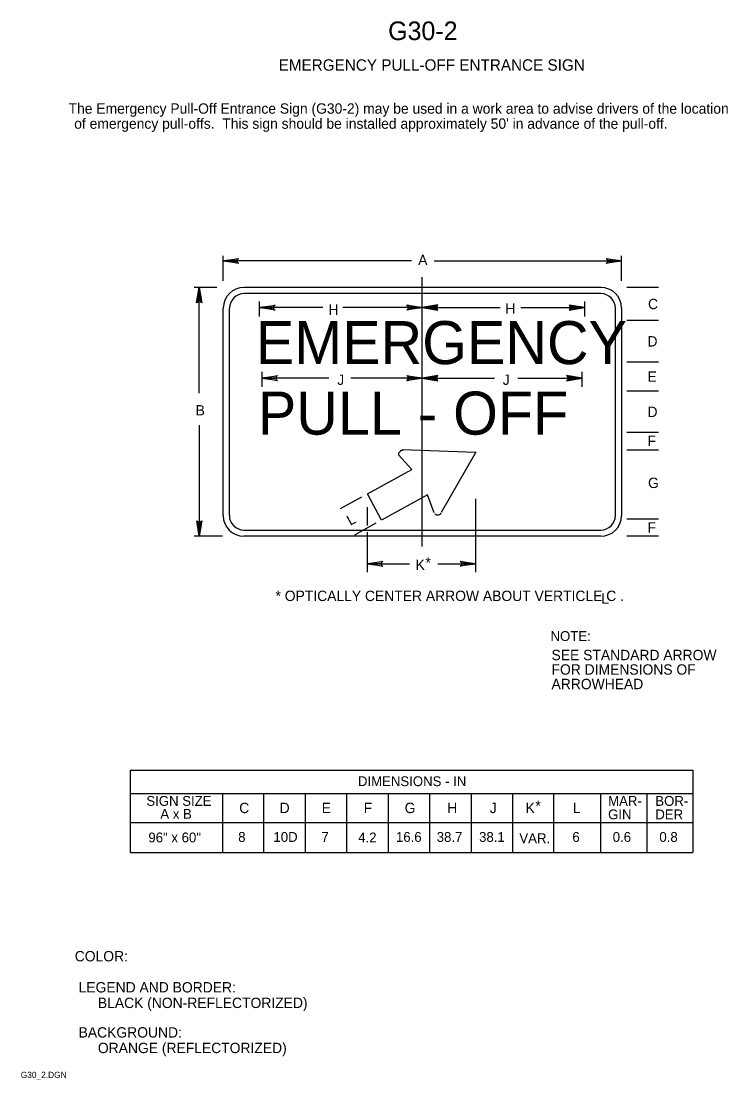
# Model space of a CAD drawing. Extents: x 0.012 to 0.182, y 0.004 to 0.259.
import ezdxf

# ---------------------------------------------------------------- set-up
doc = ezdxf.new("R2010")
doc.units = 0
doc.layers.add('1', color=7, linetype='Continuous')
doc.layers.add('3', color=7, linetype='Continuous')

# ---------------------------------------------------------------- blocks, each defined once
blk = doc.blocks.new('RARROW')
at = {"layer": '3'}
for p, q in [((-2.156, 0.285), (-2.2665, 0.384625)), ((-2.2665, 0.384625), (0, 0)), ((0, 0), (-2.2665, -0.379125)), ((-2.156, 0.285), (-2.075625, 0.12075)), ((0, 0), (-2.156, 0.285)), ((-2.14975, -0.2705), (0, 0)), ((-2.075625, 0.12075), (0, 0)), ((0, 0), (-2.074, -0.108)), ((-2.2665, -0.379125), (-2.14975, -0.2705)), ((-2.074, -0.108), (-2.14975, -0.2705))]:
    blk.add_line(p, q, dxfattribs=at)

msp = doc.modelspace()

# ---------------------------------------------------------------- linework, layer by layer
at = {"layer": '1'}
for p, q in [((0.10887, 0.1325), (0.10887, 0.1975)), ((0.06963, 0.188), (0.06963, 0.19163)), ((0.148, 0.188), (0.148, 0.19163)), ((0.07025, 0.171), (0.07025, 0.17463)), ((0.14738, 0.171), (0.14738, 0.17463)), ((0.09421, 0.14445), (0.08905, 0.14163)), ((0.12175, 0.12638), (0.12175, 0.144)), ((0.09563, 0.13762), (0.09563, 0.142)), ((0.09768, 0.13812), (0.09253, 0.1353)), ((0.09563, 0.12638), (0.09563, 0.13599))]:
    msp.add_line(p, q, dxfattribs=at)
at = {"layer": '3'}
for p, q in [((0.06087, 0.19662), (0.06087, 0.20262)), ((0.15688, 0.19662), (0.15688, 0.20262)), ((0.10625, 0.20137), (0.06087, 0.20137)), ((0.11175, 0.20137), (0.15688, 0.20137)), ((0.05938, 0.195), (0.05387, 0.195)), ((0.05513, 0.1695), (0.05513, 0.195)), ((0.15187, 0.195), (0.06588, 0.195)), ((0.16575, 0.195), (0.15813, 0.195)), ((0.15187, 0.1935), (0.06588, 0.1935)), ((0.06087, 0.14), (0.06087, 0.19)), ((0.06237, 0.19), (0.06237, 0.14)), ((0.08488, 0.19013), (0.06963, 0.19013)), ((0.10887, 0.19013), (0.08975, 0.19013)), ((0.10887, 0.19013), (0.12763, 0.19013)), ((0.13262, 0.19013), (0.148, 0.19013)), ((0.15538, 0.14), (0.15538, 0.19)), ((0.15688, 0.19), (0.15688, 0.14)), ((0.16575, 0.187), (0.15813, 0.187)), ((0.16575, 0.177), (0.15813, 0.177)), ((0.08638, 0.17313), (0.07025, 0.17313)), ((0.10887, 0.17313), (0.09162, 0.17313)), ((0.10887, 0.17313), (0.12625, 0.17313)), ((0.13187, 0.17313), (0.14738, 0.17313)), ((0.16575, 0.17), (0.15813, 0.17)), ((0.05513, 0.16175), (0.05513, 0.135)), ((0.16575, 0.16), (0.15813, 0.16)), ((0.104, 0.15588), (0.12175, 0.15525)), ((0.16575, 0.15575), (0.15813, 0.15575)), ((0.10637, 0.15113), (0.10313, 0.15463)), ((0.12175, 0.15525), (0.11338, 0.14075)), ((0.09563, 0.14525), (0.10637, 0.15113)), ((0.099, 0.13887), (0.09563, 0.14525)), ((0.11013, 0.145), (0.099, 0.13887)), ((0.11175, 0.14062), (0.11013, 0.145)), ((0.16575, 0.13912), (0.15813, 0.13912)), ((0.06588, 0.1365), (0.15187, 0.1365)), ((0.06075, 0.135), (0.05387, 0.135)), ((0.15187, 0.135), (0.06588, 0.135)), ((0.16575, 0.135), (0.15813, 0.135)), ((0.09563, 0.12837), (0.10575, 0.12837)), ((0.11263, 0.12837), (0.12175, 0.12837)), ((0.0385, 0.07863), (0.0385, 0.05875)), ((0.03853, 0.07863), (0.17408, 0.07863)), ((0.17408, 0.07863), (0.17408, 0.05877)), ((0.03853, 0.073), (0.17408, 0.073)), ((0.0607, 0.07302), (0.0607, 0.05877)), ((0.07063, 0.073), (0.07063, 0.05875)), ((0.08063, 0.073), (0.08063, 0.05875)), ((0.09062, 0.073), (0.09062, 0.05875)), ((0.10063, 0.073), (0.10063, 0.05875)), ((0.11063, 0.073), (0.11063, 0.05875)), ((0.12062, 0.073), (0.12062, 0.05875)), ((0.13062, 0.073), (0.13062, 0.05875)), ((0.14048, 0.07302), (0.14048, 0.05877)), ((0.15183, 0.07302), (0.15183, 0.05877)), ((0.16295, 0.07302), (0.16295, 0.05877)), ((0.03853, 0.066), (0.17408, 0.066)), ((0.03853, 0.05875), (0.17408, 0.05875))]:
    msp.add_line(p, q, dxfattribs=at)
for centre, radius, start, end in [((0.06592, 0.19), 0.005, 90, 180), ((0.15187, 0.19), 0.005, 0, 90), ((0.06592, 0.19), 0.0035, 90, 180), ((0.15187, 0.19), 0.0035, 0, 90), ((0.0659, 0.14002), 0.00502, 180.2208, 270.2208), ((0.0659, 0.14002), 0.00352, 180.3149, 270.3149), ((0.15187, 0.14), 0.005, 270, 0), ((0.15187, 0.14), 0.0035, 270, 0)]:
    msp.add_arc(centre, radius, start, end, dxfattribs=at)
for centre, major_axis, start_param, end_param in [((0.10398, 0.15502), (0.000809, 0.000386), 1.067247, 3.430489), ((0.11273, 0.14081), (-0.000809, -0.000386), 6.14245, 8.505692)]:
    msp.add_ellipse(centre, major_axis=major_axis, ratio=0.690486, start_param=start_param, end_param=end_param, dxfattribs=at)

# ---------------------------------------------------------------- block references
at = {"layer": '3', "xscale": 0.0016545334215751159}
for p, yscale, rotation in [((0.06087, 0.20137), 0.0016366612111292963, 180), ((0.05513, 0.195), 0.0016366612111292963, 90), ((0.06963, 0.19013), 0.0016366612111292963, 180), ((0.10887, 0.19013), -0.0016366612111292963, 180), ((0.07025, 0.17313), 0.0016366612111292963, 180), ((0.10887, 0.17313), -0.0016366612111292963, 180), ((0.05513, 0.135), 0.0016366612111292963, -90), ((0.09563, 0.12837), 0.0016366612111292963, 180)]:
    msp.add_blockref('RARROW', p, dxfattribs=dict(at, yscale=yscale, rotation=rotation))
for p, yscale in [((0.15688, 0.20137), 0.0016366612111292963), ((0.10887, 0.19013), 0.0016366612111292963), ((0.148, 0.19013), -0.0016366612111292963), ((0.10887, 0.17313), 0.0016366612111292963), ((0.14738, 0.17313), -0.0016366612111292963), ((0.12175, 0.12837), 0.0016366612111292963)]:
    msp.add_blockref('RARROW', p, dxfattribs=dict(at, yscale=yscale))

# ---------------------------------------------------------------- texts
at = {"layer": '1'}
for s, height, p in [('G30-2', 0.0045, (0.10063, 0.25462)), ('EMERGENCY PULL-OFF ENTRANCE SIGN', 0.0027503, (0.07425, 0.24725)), ('EMERGENCY', 0.010375, (0.06875, 0.1765)), ('PULL - OFF', 0.010375, (0.06925, 0.1595)), ('* OPTICALLY CENTER ARROW ABOUT VERTICLE C .', 0.0024998, (0.0735, 0.11938)), ('NOTE:', 0.002375, (0.13975, 0.10975)), ('SEE STANDARD ARROW', 0.0024998, (0.14, 0.10512)), ('FOR DIMENSIONS OF', 0.0024998, (0.14, 0.10163)), ('ARROWHEAD', 0.0025, (0.14, 0.09813)), ('COLOR:', 0.0025, (0.02513, 0.0325)), (' LEGEND AND BORDER:', 0.0024998, (0.02513, 0.025)), ('      BLACK (NON-REFLECTORIZED)', 0.0024998, (0.02513, 0.02125)), (' BACKGROUND:', 0.0024998, (0.02513, 0.01413)), ('      ORANGE (REFLECTORIZED)', 0.0024998, (0.02513, 0.01038)), ('G30_2.DGN', 0.0015, (0.01213, 0.00438))]:
    msp.add_text(s, height=height, dxfattribs=at).set_placement(p)
msp.add_text('L', height=0.0025, rotation=28.7284, dxfattribs=at).set_placement((0.0915, 0.1375))
at = {"layer": '3'}
for s, height, p in [('     The Emergency Pull-Off Entrance Sign (G30-2) may be used in a work area to advise drivers of the location', 0.00249975, (0.019, 0.23688)), ("of emergency pull-offs.  This sign should be installed approximately 50' in advance of the pull-off.", 0.0024998, (0.025, 0.23325)), ('A', 0.0025, (0.10787, 0.20037)), ('C', 0.0025, (0.16325, 0.18975)), ('H', 0.0025, (0.08625, 0.18838)), ('H', 0.0025, (0.12887, 0.18863)), ('D', 0.0025, (0.16312, 0.18075)), ('J', 0.0025, (0.08837, 0.1715)), ('J', 0.0025, (0.12825, 0.1715)), ('E', 0.0025, (0.16312, 0.17225)), ('B', 0.0025, (0.05425, 0.16412)), ('D', 0.0025, (0.16312, 0.16375)), ('F', 0.0025, (0.16312, 0.15675)), ('G', 0.0025, (0.16325, 0.14663)), ('F', 0.0025, (0.16312, 0.13587)), ('K', 0.0025, (0.10725, 0.12688)), ('*', 0.0025, (0.10963, 0.12738)), ('L', 0.0025, (0.152, 0.11875)), ('DIMENSIONS - IN', 0.0023752, (0.09335, 0.07475)), ('SIGN SIZE', 0.002375, (0.04238, 0.07)), ('MAR-', 0.002375, (0.15363, 0.07)), ('BOR-', 0.002375, (0.165, 0.07)), ('A x B', 0.002375, (0.04575, 0.06688)), ('C', 0.0025, (0.06475, 0.06825)), ('D', 0.0025, (0.0745, 0.06825)), ('E', 0.0025, (0.08463, 0.06825)), ('F', 0.0025, (0.09475, 0.06825)), ('G', 0.0025, (0.10462, 0.06825)), ('H', 0.0025, (0.11488, 0.06825)), ('J', 0.0025, (0.12513, 0.06825)), ('K', 0.0025, (0.13375, 0.06825)), ('*', 0.0025, (0.13612, 0.06875)), ('L', 0.0025, (0.14513, 0.06825)), ('GIN', 0.002375, (0.15363, 0.06675)), ('DER', 0.002375, (0.165, 0.06675)), ('96" x 60"', 0.002375, (0.04287, 0.06119)), ('8', 0.00238, (0.06451, 0.06131)), ('10D', 0.002375, (0.073, 0.06131)), ('7', 0.00238, (0.08456, 0.06131)), ('4.2', 0.002375, (0.09342, 0.06119)), ('16.6', 0.002375, (0.10252, 0.06131)), ('38.7', 0.002375, (0.11234, 0.06131)), ('38.1', 0.002375, (0.12255, 0.06131)), ('VAR.', 0.002375, (0.13225, 0.061)), ('6', 0.00238, (0.14502, 0.06131)), ('0.6', 0.002375, (0.15474, 0.06131)), ('0.8', 0.002375, (0.16598, 0.06131))]:
    msp.add_text(s, height=height, dxfattribs=at).set_placement(p)

doc.saveas('drawing.dxf')
